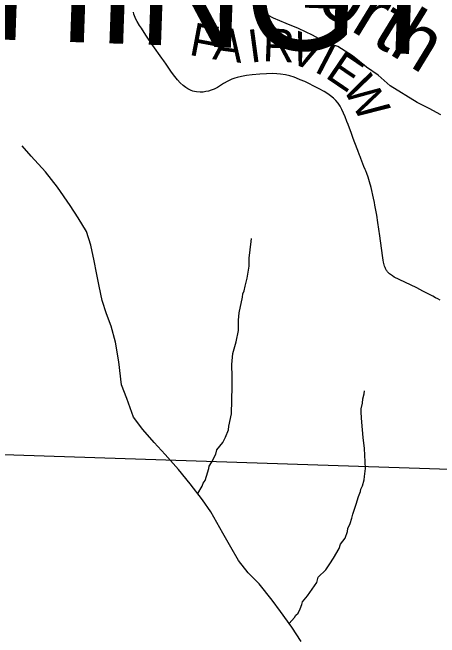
# Model space of a CAD drawing. Extents: x 6.3 to 40.3, y 9 to 31.
# Drawn here: x 10.406 to 11.141, y 27.918 to 28.995 of the extents above; entities that cross this region are included whole.
import ezdxf

# ---------------------------------------------------------------- set-up
doc = ezdxf.new("R2010")
doc.units = 0
for name, color, linetype in [('GM_X_County_Text', 7, 'Continuous'), ('GM_X_Minor_River', 7, 'Continuous'), ('GM_X_Minor_River_Text', 7, 'Continuous'), ('GM_X_Section', 7, 'Continuous'), ('GM_X_Township_Road', 7, 'Continuous'), ('GM_X_Township_Road_Text', 7, 'Continuous')]:
    doc.layers.add(name, color=color, linetype=linetype)

msp = doc.modelspace()

# ---------------------------------------------------------------- linework, layer by layer
at = {"layer": 'GM_X_Minor_River'}
for points in [[(11.1434, 28.8184), (11.1234, 28.8294), (11.1026, 28.8399), (11.0564, 28.8683), (11.0356, 28.8868), (11.0155, 28.9007), (10.9916, 28.92), (10.9659, 28.9359), (10.9443, 28.9438), (10.9224, 28.9559), (10.8985, 28.9672), (10.877, 28.9759), (10.8554, 28.985), (10.8459, 28.9899)], [(10.9029, 27.9114), (10.887, 27.9363), (10.8677, 27.9631), (10.8533, 27.9828), (10.831, 28.0107), (10.8117, 28.0296), (10.795, 28.0511), (10.7818, 28.0738), (10.7682, 28.0983), (10.7477, 28.1349), (10.733, 28.1557), (10.7118, 28.1829), (10.6921, 28.2078), (10.669, 28.2335), (10.6501, 28.2543), (10.6308, 28.2765), (10.6145, 28.2981), (10.6031, 28.3302), (10.5941, 28.3536), (10.5895, 28.3929), (10.5835, 28.4272), (10.5759, 28.4544), (10.5683, 28.4756), (10.5608, 28.499), (10.5555, 28.5235), (10.5506, 28.5466), (10.5468, 28.5673), (10.5411, 28.5938), (10.5339, 28.6176), (10.5195, 28.6413), (10.5055, 28.6621), (10.484, 28.6938), (10.4632, 28.7206), (10.4386, 28.7475), (10.4227, 28.7652)], [(10.7251, 28.1665), (10.7329, 28.1792), (10.7343, 28.1841), (10.7381, 28.1887), (10.7399, 28.196), (10.744, 28.2093), (10.7447, 28.2135), (10.7488, 28.22), (10.7562, 28.2341), (10.758, 28.2418), (10.7682, 28.2544), (10.7726, 28.2632), (10.7778, 28.2758), (10.7785, 28.2826), (10.7832, 28.3036), (10.7842, 28.3507), (10.7841, 28.3674), (10.7835, 28.3887), (10.7852, 28.4073), (10.7914, 28.4275), (10.795, 28.4469), (10.7952, 28.4648), (10.7966, 28.4773), (10.802, 28.5044), (10.8027, 28.5101), (10.8049, 28.5154), (10.8064, 28.5234), (10.8104, 28.5375), (10.8136, 28.5577), (10.8138, 28.5717), (10.8169, 28.6003), (10.8173, 28.6056)], [(10.8824, 27.9427), (10.8917, 27.9529), (10.8936, 27.9571), (10.8977, 27.9602), (10.9014, 27.9678), (10.9044, 27.9751), (10.9051, 27.9797), (10.9141, 27.9904), (10.9298, 28.0134), (10.9324, 28.0225), (10.9455, 28.0348), (10.9526, 28.0455), (10.9586, 28.0551), (10.9687, 28.0719), (10.9705, 28.0791), (10.9787, 28.0895), (10.9828, 28.1009), (10.9831, 28.1059), (10.9872, 28.115), (10.9902, 28.1242), (10.992, 28.1307), (10.9979, 28.1482), (11.0015, 28.1615), (11.0049, 28.1699), (11.0056, 28.1741), (11.0086, 28.1798), (11.0115, 28.1901), (11.0118, 28.1958), (11.0139, 28.2092), (11.0126, 28.2327), (11.0121, 28.2441), (11.01, 28.2627), (11.0074, 28.2892), (11.007, 28.2968), (11.0061, 28.3063), (11.0064, 28.3124), (11.0086, 28.3219), (11.0089, 28.3295), (11.0115, 28.3383), (11.0118, 28.3432)]]:
    msp.add_lwpolyline(points, dxfattribs=at)
at = {"layer": 'GM_X_Section'}
msp.add_lwpolyline([(10.3378, 28.2352), (11.3334, 28.2025), (11.3031, 27.2038), (10.3113, 27.232)], close=True, dxfattribs=at)
at = {"layer": 'GM_X_Township_Road'}
msp.add_lwpolyline([(11.1421, 28.4995), (11.1382, 28.5015), (11.1344, 28.5035), (11.1294, 28.506), (11.1122, 28.5147), (11.1018, 28.5203), (11.0716, 28.5349), (11.0633, 28.5391), (11.0601, 28.541), (11.0583, 28.5422), (11.0565, 28.5435), (11.0551, 28.5447), (11.0537, 28.5459), (11.0526, 28.5472), (11.0516, 28.5482), (11.0508, 28.5493), (11.05, 28.5505), (11.0494, 28.5515), (11.0489, 28.5525), (11.0482, 28.5539), (11.0474, 28.5558), (11.0466, 28.5578), (11.0459, 28.5599), (11.0452, 28.5624), (11.0446, 28.5647), (11.044, 28.568), (11.0433, 28.572), (11.041, 28.5886), (11.0384, 28.6102), (11.0352, 28.633), (11.0332, 28.6459), (11.03, 28.663), (11.029, 28.6678), (11.0274, 28.6751), (11.0234, 28.6933), (11.0209, 28.7029), (11.0184, 28.7112), (11.0161, 28.7177), (11.0141, 28.7222), (11.0133, 28.7245), (11.0111, 28.7297), (11.0093, 28.7343), (11.0057, 28.7435), (11.0046, 28.7465), (11.0035, 28.7493), (11.0005, 28.7569), (10.9954, 28.7702), (10.9926, 28.7778), (10.9894, 28.7865), (10.9839, 28.8017), (10.9819, 28.8069), (10.9787, 28.815), (10.976, 28.8213), (10.9732, 28.8275), (10.9699, 28.8335), (10.9665, 28.8386), (10.9629, 28.8429), (10.9586, 28.8472), (10.9538, 28.8511), (10.9487, 28.8546), (10.9424, 28.8584), (10.9338, 28.8631), (10.9246, 28.8681), (10.9163, 28.8724), (10.9096, 28.8756), (10.9015, 28.8789), (10.8953, 28.8816), (10.8912, 28.8831), (10.8835, 28.8855), (10.8763, 28.8874), (10.8677, 28.8885), (10.8609, 28.8892), (10.8535, 28.8894), (10.8435, 28.8892), (10.8318, 28.8884), (10.8188, 28.8872), (10.8089, 28.8861), (10.8003, 28.8847), (10.793, 28.883), (10.7889, 28.8817), (10.7837, 28.8798), (10.777, 28.8765), (10.7695, 28.8722), (10.7589, 28.8656), (10.7534, 28.8628), (10.7482, 28.8607), (10.7434, 28.8592), (10.7392, 28.8584), (10.7343, 28.8578), (10.7293, 28.8578), (10.7229, 28.8582), (10.7194, 28.8587), (10.7164, 28.8594), (10.7136, 28.8604), (10.7113, 28.8614), (10.7081, 28.8632), (10.7044, 28.8656), (10.7001, 28.8691), (10.6951, 28.8737), (10.6903, 28.8787), (10.6856, 28.8844), (10.6801, 28.892), (10.6705, 28.9057), (10.6666, 28.9113), (10.6633, 28.9158), (10.648, 28.9377), (10.6359, 28.9558), (10.6281, 28.9677), (10.6251, 28.9724), (10.6209, 28.9794), (10.6188, 28.9832), (10.6176, 28.986), (10.6164, 28.9889), (10.6153, 28.9921), (10.6146, 28.9955)], dxfattribs=at)

# ---------------------------------------------------------------- texts
at = {"layer": 'GM_X_County_Text'}
msp.add_text('WASHINGTON COUNTY', height=0.189394, rotation=357.9773, dxfattribs=at).set_placement((9.7904, 28.9692))
at = {"layer": 'GM_X_Minor_River_Text'}
msp.add_text('North', height=0.0947, rotation=328.5956, dxfattribs=at).set_placement((10.8475, 29.0494))
at = {"layer": 'GM_X_Township_Road_Text'}
for s, rotation, p in [('F', 349.3144, (10.7085, 28.9221)), ('A', 352.498, (10.7496, 28.9144)), ('I', 7.7088, (10.8156, 28.9079)), ('R', 357.7395, (10.8361, 28.9109)), ('V', 340.2609, (10.8782, 28.91)), ('I', 332.5134, (10.9234, 28.8939)), ('E', 325.8345, (10.9426, 28.884)), ('W', 299.469, (10.9732, 28.8652))]:
    msp.add_text(s, height=0.0568, rotation=rotation, dxfattribs=at).set_placement(p)

doc.saveas('drawing.dxf')
